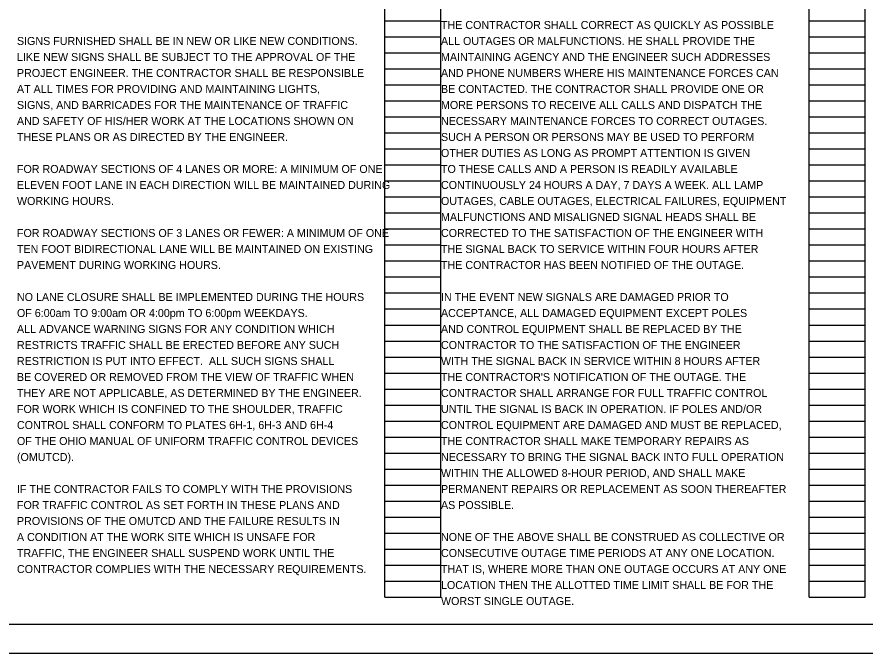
# Model space of a CAD drawing. Extents: x -6 to 34, y 0 to 22.
# Drawn here: x 2.4 to 17.24, y 0 to 11.13 of the extents above; entities that cross this region are included whole.
import ezdxf

# ---------------------------------------------------------------- set-up
doc = ezdxf.new("R2010")
doc.units = 0
for name, color, linetype in [('Default', 7, 'Continuous'), ('SH_Border', 7, 'Continuous'), ('SH_Cut_Line', 7, 'Continuous'), ('SH_Data', 7, 'Continuous'), ('SH_Text', 7, 'Continuous')]:
    doc.layers.add(name, color=color, linetype=linetype)

msp = doc.modelspace()

# ---------------------------------------------------------------- linework, layer by layer
at = {"layer": 'SH_Border'}
msp.add_lwpolyline([(1.5, 21.5), (33.5, 21.5), (33.5, 0.5), (1.5, 0.5)], close=True, dxfattribs=at)
at = {"layer": 'SH_Cut_Line'}
msp.add_lwpolyline([(0, 0), (34, 0), (34, 22), (0, 22)], close=True, dxfattribs=at)
at = {"layer": 'SH_Data'}
for p, q in [((8.84, 0.98), (8.84, 21.14)), ((9.82, 0.98), (9.82, 21.14)), ((16.26, 0.98), (16.26, 21.14)), ((17.24, 0.98), (17.24, 21.14)), ((8.84, 11.06), (9.82, 11.06)), ((16.26, 11.06), (17.24, 11.06)), ((8.84, 10.78), (9.82, 10.78)), ((16.26, 10.78), (17.24, 10.78)), ((8.84, 10.5), (9.82, 10.5)), ((16.26, 10.5), (17.24, 10.5)), ((8.84, 10.22), (9.82, 10.22)), ((16.26, 10.22), (17.24, 10.22)), ((8.84, 9.94), (9.82, 9.94)), ((16.26, 9.94), (17.24, 9.94)), ((8.84, 9.66), (9.82, 9.66)), ((16.26, 9.66), (17.24, 9.66)), ((8.84, 9.38), (9.82, 9.38)), ((16.26, 9.38), (17.24, 9.38)), ((8.84, 9.1), (9.82, 9.1)), ((16.26, 9.1), (17.24, 9.1)), ((8.84, 8.82), (9.82, 8.82)), ((16.26, 8.82), (17.24, 8.82)), ((8.84, 8.54), (9.82, 8.54)), ((16.26, 8.54), (17.24, 8.54)), ((8.84, 8.26), (9.82, 8.26)), ((16.26, 8.26), (17.24, 8.26)), ((8.84, 7.98), (9.82, 7.98)), ((16.26, 7.98), (17.24, 7.98)), ((8.84, 7.7), (9.82, 7.7)), ((16.26, 7.7), (17.24, 7.7)), ((8.84, 7.42), (9.82, 7.42)), ((16.26, 7.42), (17.24, 7.42)), ((8.84, 7.14), (9.82, 7.14)), ((16.26, 7.14), (17.24, 7.14)), ((8.84, 6.86), (9.82, 6.86)), ((16.26, 6.86), (17.24, 6.86)), ((8.84, 6.58), (9.82, 6.58)), ((16.26, 6.58), (17.24, 6.58)), ((8.84, 6.3), (9.82, 6.3)), ((16.26, 6.3), (17.24, 6.3)), ((8.84, 6.02), (9.82, 6.02)), ((16.26, 6.02), (17.24, 6.02)), ((8.84, 5.74), (9.82, 5.74)), ((16.26, 5.74), (17.24, 5.74)), ((8.84, 5.46), (9.82, 5.46)), ((16.26, 5.46), (17.24, 5.46)), ((8.84, 5.18), (9.82, 5.18)), ((16.26, 5.18), (17.24, 5.18)), ((8.84, 4.9), (9.82, 4.9)), ((16.26, 4.9), (17.24, 4.9)), ((8.84, 4.62), (9.82, 4.62)), ((16.26, 4.62), (17.24, 4.62)), ((8.84, 4.34), (9.82, 4.34)), ((16.26, 4.34), (17.24, 4.34)), ((8.84, 4.06), (9.82, 4.06)), ((16.26, 4.06), (17.24, 4.06)), ((8.84, 3.78), (9.82, 3.78)), ((16.26, 3.78), (17.24, 3.78)), ((8.84, 3.5), (9.82, 3.5)), ((16.26, 3.5), (17.24, 3.5)), ((8.84, 3.22), (9.82, 3.22)), ((16.26, 3.22), (17.24, 3.22)), ((8.84, 2.94), (9.82, 2.94)), ((16.26, 2.94), (17.24, 2.94)), ((8.84, 2.66), (9.82, 2.66)), ((16.26, 2.66), (17.24, 2.66)), ((8.84, 2.38), (9.82, 2.38)), ((16.26, 2.38), (17.24, 2.38)), ((8.84, 2.1), (9.82, 2.1)), ((16.26, 2.1), (17.24, 2.1)), ((8.84, 1.82), (9.82, 1.82)), ((16.26, 1.82), (17.24, 1.82)), ((8.84, 1.54), (9.82, 1.54)), ((16.26, 1.54), (17.24, 1.54)), ((8.84, 1.26), (9.82, 1.26)), ((16.26, 1.26), (17.24, 1.26)), ((8.84, 0.98), (9.82, 0.98)), ((16.26, 0.98), (17.24, 0.98))]:
    msp.add_line(p, q, dxfattribs=at)

# ---------------------------------------------------------------- texts
at = {"layer": 'Default'}
for s, p in [('FOR ROADWAY SECTIONS OF 4 LANES OR MORE: A MINIMUM OF ONE ', (2.4, 8.4)), ('ELEVEN FOOT LANE IN EACH DIRECTION WILL BE MAINTAINED DURING ', (2.4, 8.12)), ('WORKING HOURS.', (2.4, 7.84)), ('FOR ROADWAY SECTIONS OF 3 LANES OR FEWER: A MINIMUM OF ONE ', (2.4, 7.28)), ('TEN FOOT BIDIRECTIONAL LANE WILL BE MAINTAINED ON EXISTING ', (2.4, 7)), ('PAVEMENT DURING WORKING HOURS.', (2.4, 6.72))]:
    msp.add_text(s, height=0.14, dxfattribs=at).set_placement(p)
at = {"layer": 'SH_Text'}
for s, p in [('THE CONTRACTOR SHALL CORRECT AS QUICKLY AS POSSIBLE', (9.82, 10.92)), ('SIGNS FURNISHED SHALL BE IN NEW OR LIKE NEW CONDITIONS.', (2.4, 10.64)), ('ALL OUTAGES OR MALFUNCTIONS. HE SHALL PROVIDE THE', (9.82, 10.64)), ('LIKE NEW SIGNS SHALL BE SUBJECT TO THE APPROVAL OF THE', (2.4, 10.36)), ('MAINTAINING AGENCY AND THE ENGINEER SUCH ADDRESSES', (9.82, 10.36)), ('PROJECT ENGINEER. THE CONTRACTOR SHALL BE RESPONSIBLE', (2.4, 10.08)), ('AND PHONE NUMBERS WHERE HIS MAINTENANCE FORCES CAN', (9.82, 10.08)), ('AT ALL TIMES FOR PROVIDING AND MAINTAINING LIGHTS,', (2.4, 9.8)), ('BE CONTACTED. THE CONTRACTOR SHALL PROVIDE ONE OR', (9.82, 9.8)), ('SIGNS, AND BARRICADES FOR THE MAINTENANCE OF TRAFFIC', (2.4, 9.52)), ('MORE PERSONS TO RECEIVE ALL CALLS AND DISPATCH THE', (9.82, 9.52)), ('AND SAFETY OF HIS/HER WORK AT THE LOCATIONS SHOWN ON', (2.4, 9.24)), ('NECESSARY MAINTENANCE FORCES TO CORRECT OUTAGES.', (9.82, 9.24)), ('THESE PLANS OR AS DIRECTED BY THE ENGINEER.', (2.4, 8.96)), ('SUCH A PERSON OR PERSONS MAY BE USED TO PERFORM', (9.82, 8.96)), ('OTHER DUTIES AS LONG AS PROMPT ATTENTION IS GIVEN', (9.82, 8.68)), ('TO THESE CALLS AND A PERSON IS READILY AVAILABLE', (9.82, 8.4)), ('CONTINUOUSLY 24 HOURS A DAY, 7 DAYS A WEEK. ALL LAMP', (9.82, 8.12)), ('OUTAGES, CABLE OUTAGES, ELECTRICAL FAILURES, EQUIPMENT', (9.82, 7.84)), ('MALFUNCTIONS AND MISALIGNED SIGNAL HEADS SHALL BE', (9.82, 7.56)), ('CORRECTED TO THE SATISFACTION OF THE ENGINEER WITH', (9.82, 7.28)), ('THE SIGNAL BACK TO SERVICE WITHIN FOUR HOURS AFTER', (9.82, 7)), ('THE CONTRACTOR HAS BEEN NOTIFIED OF THE OUTAGE.', (9.82, 6.72)), ('NO LANE CLOSURE SHALL BE IMPLEMENTED DURING THE HOURS', (2.4, 6.16)), ('IN THE EVENT NEW SIGNALS ARE DAMAGED PRIOR TO', (9.82, 6.16)), ('OF 6:00am TO 9:00am OR 4:00pm TO 6:00pm WEEKDAYS.', (2.4, 5.88)), ('ACCEPTANCE, ALL DAMAGED EQUIPMENT EXCEPT POLES', (9.82, 5.88)), ('ALL ADVANCE WARNING SIGNS FOR ANY CONDITION WHICH', (2.4, 5.6)), ('AND CONTROL EQUIPMENT SHALL BE REPLACED BY THE', (9.82, 5.6)), ('RESTRICTS TRAFFIC SHALL BE ERECTED BEFORE ANY SUCH', (2.4, 5.32)), ('CONTRACTOR TO THE SATISFACTION OF THE ENGINEER', (9.82, 5.32)), ('RESTRICTION IS PUT INTO EFFECT.  ALL SUCH SIGNS SHALL', (2.4, 5.04)), ('WITH THE SIGNAL BACK IN SERVICE WITHIN 8 HOURS AFTER', (9.82, 5.04)), ('BE COVERED OR REMOVED FROM THE VIEW OF TRAFFIC WHEN', (2.4, 4.76)), ("THE CONTRACTOR'S NOTIFICATION OF THE OUTAGE. THE", (9.82, 4.76)), ('THEY ARE NOT APPLICABLE, AS DETERMINED BY THE ENGINEER.', (2.4, 4.48)), ('CONTRACTOR SHALL ARRANGE FOR FULL TRAFFIC CONTROL', (9.82, 4.48)), ('FOR WORK WHICH IS CONFINED TO THE SHOULDER, TRAFFIC', (2.4, 4.2)), ('UNTIL THE SIGNAL IS BACK IN OPERATION. IF POLES AND/OR', (9.82, 4.2)), ('CONTROL SHALL CONFORM TO PLATES 6H-1, 6H-3 AND 6H-4', (2.4, 3.92)), ('CONTROL EQUIPMENT ARE DAMAGED AND MUST BE REPLACED,', (9.82, 3.92)), ('OF THE OHIO MANUAL OF UNIFORM TRAFFIC CONTROL DEVICES', (2.4, 3.64)), ('THE CONTRACTOR SHALL MAKE TEMPORARY REPAIRS AS', (9.82, 3.64)), ('(OMUTCD).', (2.4, 3.36)), ('NECESSARY TO BRING THE SIGNAL BACK INTO FULL OPERATION', (9.82, 3.36)), ('WITHIN THE ALLOWED 8-HOUR PERIOD, AND SHALL MAKE', (9.82, 3.08)), ('IF THE CONTRACTOR FAILS TO COMPLY WITH THE PROVISIONS', (2.4, 2.8)), ('PERMANENT REPAIRS OR REPLACEMENT AS SOON THEREAFTER', (9.82, 2.8)), ('FOR TRAFFIC CONTROL AS SET FORTH IN THESE PLANS AND', (2.4, 2.52)), ('AS POSSIBLE.', (9.82, 2.52)), ('PROVISIONS OF THE OMUTCD AND THE FAILURE RESULTS IN', (2.4, 2.24)), ('A CONDITION AT THE WORK SITE WHICH IS UNSAFE FOR', (2.4, 1.96)), ('NONE OF THE ABOVE SHALL BE CONSTRUED AS COLLECTIVE OR', (9.82, 1.96)), ('TRAFFIC, THE ENGINEER SHALL SUSPEND WORK UNTIL THE', (2.4, 1.68)), ('CONSECUTIVE OUTAGE TIME PERIODS AT ANY ONE LOCATION.', (9.82, 1.68)), ('CONTRACTOR COMPLIES WITH THE NECESSARY REQUIREMENTS.', (2.4, 1.4)), ('THAT IS, WHERE MORE THAN ONE OUTAGE OCCURS AT ANY ONE', (9.82, 1.4)), ('LOCATION THEN THE ALLOTTED TIME LIMIT SHALL BE FOR THE', (9.82, 1.12)), ('WORST SINGLE OUTAGE.', (9.82, 0.84))]:
    msp.add_text(s, height=0.14, dxfattribs=at).set_placement(p)

doc.saveas('drawing.dxf')
